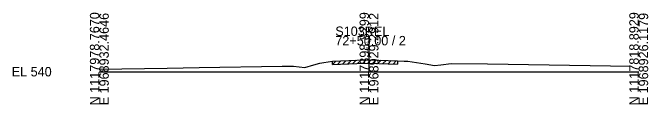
# Model space of a CAD drawing. Extents: x -26 to 163, y -10 to 24518.
# Drawn here: x -25.7 to 162.8, y 20990.3 to 21017.5 of the extents above; entities that cross this region are included whole.
import ezdxf

# ---------------------------------------------------------------- set-up
doc = ezdxf.new("R2010")
doc.units = 0
for name, color, linetype in [('RD_GPK_XS_Cell', 7, 'Continuous'), ('RD_XS_ExGround', 7, 'Continuous'), ('RD_XS_ExPaveRet', 7, 'Continuous'), ('RD_XS_TX_Elev_EX', 7, 'Continuous')]:
    doc.layers.add(name, color=color, linetype=linetype)

msp = doc.modelspace()

# ---------------------------------------------------------------- linework, layer by layer
at = {"layer": 'RD_GPK_XS_Cell'}
for p, q in [((80, 21000), (80, 21010.63)), ((0, 21000), (80, 21000)), ((80, 21000), (160, 21000))]:
    msp.add_line(p, q, dxfattribs=at)
at = {"layer": 'RD_XS_ExGround'}
msp.add_lwpolyline([(0, 21000.73), (20.11, 21001.05), (29.58, 21001.27), (54.25, 21001.61), (57.15, 21001.64), (57.57, 21001.61), (60.95, 21001.26), (63.66, 21002.04), (65.42, 21002.54), (66.62, 21002.72), (69.13, 21003.11), (76.38, 21003.4), (80.08, 21003.54), (82.92, 21003.44), (88.47, 21003.24), (90.43, 21003.15), (91.49, 21003.1), (96.62, 21002.31), (99.43, 21001.87), (101.26, 21002.09), (104.41, 21002.45), (115.13, 21002.31), (157.72, 21001.67)], dxfattribs=at)
at = {"layer": 'RD_XS_ExPaveRet'}
for p, q in [((69.13, 21002.11), (70.17, 21003.15)), ((69.13, 21002.11), (69.13, 21003.11)), ((70.63, 21002.17), (71.67, 21003.21)), ((72.13, 21002.23), (73.17, 21003.27)), ((73.63, 21002.29), (74.67, 21003.33)), ((75.13, 21002.35), (76.17, 21003.39)), ((76.38, 21002.4), (80.08, 21002.54)), ((76.63, 21002.41), (77.67, 21003.45)), ((78.13, 21002.47), (79.17, 21003.51)), ((79.63, 21002.53), (80.62, 21003.52)), ((80.08, 21002.54), (82.92, 21002.44)), ((81.13, 21002.51), (82.09, 21003.47)), ((82.63, 21002.45), (83.59, 21003.42)), ((84.13, 21002.4), (85.09, 21003.36)), ((85.63, 21002.34), (86.59, 21003.31)), ((87.13, 21002.29), (88.09, 21003.26)), ((88.47, 21003.24), (88.47, 21002.24)), ((69.13, 21002.11), (76.38, 21002.4)), ((82.92, 21002.44), (88.47, 21002.24))]:
    msp.add_line(p, q, dxfattribs=at)

# ---------------------------------------------------------------- texts
at = {"layer": 'RD_GPK_XS_Cell'}
for s, p in [('N 1117978.7670', (0, 20990)), ('E 1968932.4646', (2.8, 20990)), ('N 1117898.8299', (80, 20990)), ('E 1968929.2912', (82.8, 20990)), ('N 1117818.8929', (160, 20990)), ('E 1968926.1179', (162.8, 20990))]:
    msp.add_text(s, height=2.8, rotation=90, dxfattribs=at).set_placement(p)
for s, p in [('S103REL', (70, 21010.63)), ('72+50.00 / 2', (70, 21007.83)), ('EL 540', (-26, 20998.6))]:
    msp.add_text(s, height=2.8, dxfattribs=at).set_placement(p)
at = {"layer": 'RD_XS_TX_Elev_EX'}
msp.add_text('543.54', height=0.8, rotation=90, dxfattribs=at).set_placement((79.9, 21005.54))

doc.saveas('drawing.dxf')
